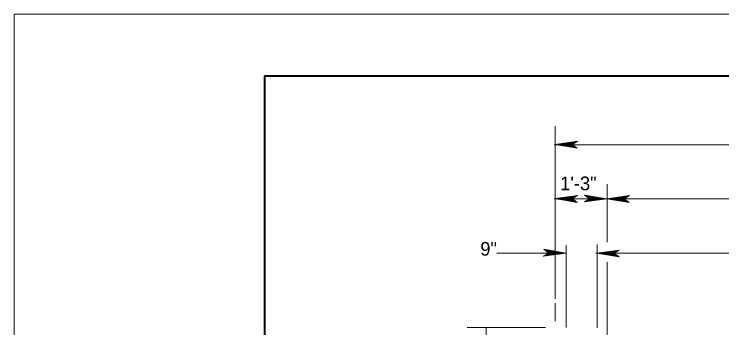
# Model space of a CAD drawing. Extents: x 144 to 252, y 360 to 425.
# Drawn here: x 143.81 to 160.77, y 417.96 to 425.48 of the extents above; entities that cross this region are included whole.
import ezdxf
from ezdxf.enums import TextEntityAlignment as Align

# ---------------------------------------------------------------- set-up
doc = ezdxf.new("R2010")
doc.units = 0
doc.header["$LTSCALE"] = 0.13
for name, color, linetype, lineweight in [('1', 7, 'Continuous', 40), ('16', 7, 'Continuous', 13), ('3', 7, 'Continuous', 13)]:
    doc.layers.add(name, color=color, linetype=linetype, lineweight=lineweight)

msp = doc.modelspace()

# ---------------------------------------------------------------- linework, layer by layer
at = {"layer": '1', "lineweight": 13}
for p, q in [((143.8112, 425.4823), (251.8112, 425.4823)), ((156.7812, 418.655), (156.7812, 421.0621)), ((157.7812, 419.2818), (157.7812, 419.9572)), ((157.0247, 419.7488), (155.3838, 419.7488)), ((177.7937, 419.7488), (157.751, 419.7488)), ((157.7812, 418.7965), (157.7812, 419.2818)), ((157.7812, 417.9642), (157.7812, 419.1343)), ((156.7812, 418.1206), (156.7812, 418.4672))]:
    msp.add_line(p, q, dxfattribs=at)
at = {"layer": '1'}
msp.add_lwpolyline([(250.3172, 361.9183), (250.3172, 423.9913), (149.8112, 423.9913), (149.8112, 361.9183), (230.3642, 361.9183)], dxfattribs=at)
at = {"layer": '16'}
msp.add_line((143.8112, 360.4183), (143.8112, 425.4823), dxfattribs=at)
at = {"layer": '3'}
for p, q in [((156.7812, 420.8483), (156.7812, 422.7941)), ((157.3177, 422.438), (156.7689, 422.3603)), ((156.7689, 422.3603), (157.3066, 422.271)), ((157.1843, 422.3603), (156.7689, 422.3603)), ((157.3117, 422.4345), (156.7833, 422.3596)), ((156.7833, 422.3596), (157.3033, 422.2733)), ((157.3082, 422.4325), (156.7942, 422.3596)), ((156.7942, 422.3596), (157.3001, 422.2757)), ((157.3036, 422.4298), (156.8086, 422.3596)), ((156.8086, 422.3596), (157.2958, 422.2788)), ((157.2995, 422.4274), (156.8213, 422.3596)), ((157.2995, 422.4274), (156.8213, 422.3596)), ((156.8213, 422.3596), (157.2921, 422.2815)), ((157.2958, 422.4253), (156.8327, 422.3596)), ((156.8327, 422.3596), (157.2887, 422.2839)), ((157.2912, 422.4226), (156.8471, 422.3596)), ((156.8471, 422.3596), (157.2845, 422.2871)), ((157.2872, 422.4202), (156.8598, 422.3596)), ((156.8598, 422.3596), (157.2807, 422.2898)), ((157.2827, 422.4177), (156.8736, 422.3596)), ((156.8736, 422.3596), (157.2767, 422.2928)), ((157.2783, 422.4151), (156.8874, 422.3596)), ((156.8874, 422.3596), (157.2726, 422.2957)), ((157.2741, 422.4126), (156.9007, 422.3596)), ((156.9007, 422.3596), (157.2687, 422.2986)), ((157.2696, 422.4099), (156.9146, 422.3596)), ((156.9146, 422.3596), (157.2646, 422.3016)), ((157.2656, 422.4077), (156.9272, 422.3596)), ((156.9272, 422.3596), (157.2608, 422.3042)), ((157.2618, 422.4054), (156.9386, 422.3596)), ((156.9386, 422.3596), (157.2574, 422.3067)), ((157.2568, 422.4026), (156.9543, 422.3596)), ((156.9543, 422.3596), (157.2528, 422.3101)), ((157.2524, 422.3999), (156.9681, 422.3596)), ((156.9681, 422.3596), (157.2488, 422.3131)), ((157.2452, 422.3957), (156.9861, 422.3591)), ((156.9861, 422.3591), (157.2445, 422.3162)), ((157.2484, 422.3977), (156.9877, 422.3607)), ((157.2408, 422.3932), (157, 422.3591)), ((157, 422.3591), (157.2403, 422.3192)), ((157.2366, 422.3907), (157.0132, 422.3591)), ((157.0132, 422.3591), (157.2365, 422.322)), ((157.2351, 422.3898), (157.0222, 422.3596)), ((157.0222, 422.3596), (157.2327, 422.3247)), ((157.2312, 422.3876), (157.0342, 422.3596)), ((157.0342, 422.3596), (157.2292, 422.3273)), ((157.2267, 422.3849), (157.0481, 422.3596)), ((157.0481, 422.3596), (157.2251, 422.3303)), ((157.2217, 422.3821), (157.0637, 422.3596)), ((157.0637, 422.3596), (157.2204, 422.3336)), ((157.2177, 422.3797), (157.0763, 422.3596)), ((157.0763, 422.3596), (157.2167, 422.3363)), ((157.2134, 422.3772), (157.0896, 422.3596)), ((157.0896, 422.3596), (157.2128, 422.3392)), ((157.2096, 422.3749), (157.1016, 422.3596)), ((157.1016, 422.3596), (157.2092, 422.3418)), ((157.2049, 422.3723), (157.1161, 422.3596)), ((157.1161, 422.3596), (157.205, 422.3448)), ((157.2005, 422.3697), (157.1299, 422.3596)), ((157.1299, 422.3596), (157.2008, 422.3478)), ((157.1964, 422.3673), (157.1426, 422.3596)), ((157.1426, 422.3596), (157.1972, 422.3506)), ((157.1558, 422.3596), (157.1933, 422.3534)), ((157.1912, 422.3642), (157.1661, 422.3607)), ((157.1885, 422.3627), (157.1672, 422.3596)), ((157.1672, 422.3596), (157.1898, 422.3558)), ((157.1774, 422.3596), (157.1868, 422.3581)), ((157.1841, 422.3601), (157.3177, 422.438)), ((157.3066, 422.271), (157.1841, 422.3601)), ((156.7562, 422.3458), (180.7569, 422.3458)), ((156.7812, 420.8483), (156.7812, 421.4067)), ((158.027, 420.0186), (158.027, 421.4067)), ((156.7571, 421.0507), (179.4617, 421.0507)), ((157.3188, 421.1359), (156.7701, 421.0582)), ((156.7701, 421.0582), (157.3077, 420.9689)), ((157.1855, 421.0582), (156.7701, 421.0582)), ((157.3128, 421.1324), (156.7845, 421.0575)), ((156.7845, 421.0575), (157.3045, 420.9712)), ((157.3093, 421.1304), (156.7953, 421.0575)), ((156.7953, 421.0575), (157.3012, 420.9736)), ((157.3047, 421.1277), (156.8098, 421.0575)), ((156.8098, 421.0575), (157.297, 420.9767)), ((157.3007, 421.1253), (156.8225, 421.0575)), ((157.3007, 421.1253), (156.8225, 421.0575)), ((156.8225, 421.0575), (157.2933, 420.9794)), ((157.297, 421.1232), (156.8338, 421.0575)), ((156.8338, 421.0575), (157.2899, 420.9818)), ((157.2924, 421.1205), (156.8483, 421.0575)), ((156.8483, 421.0575), (157.2857, 420.985)), ((157.2883, 421.1181), (156.861, 421.0575)), ((156.861, 421.0575), (157.2819, 420.9878)), ((157.2839, 421.1156), (156.8748, 421.0575)), ((156.8748, 421.0575), (157.2778, 420.9907)), ((157.2795, 421.113), (156.8886, 421.0575)), ((156.8886, 421.0575), (157.2738, 420.9937)), ((157.2752, 421.1105), (156.9018, 421.0575)), ((156.9018, 421.0575), (157.2698, 420.9965)), ((157.2707, 421.1078), (156.9158, 421.0575)), ((156.9158, 421.0575), (157.2657, 420.9995)), ((157.2668, 421.1056), (156.9283, 421.0575)), ((156.9283, 421.0575), (157.262, 421.0022)), ((157.263, 421.1033), (156.9398, 421.0575)), ((156.9398, 421.0575), (157.2586, 421.0047)), ((157.258, 421.1005), (156.9554, 421.0575)), ((156.9554, 421.0575), (157.254, 421.008)), ((157.2536, 421.0978), (156.9692, 421.0575)), ((156.9692, 421.0575), (157.2499, 421.011)), ((157.2464, 421.0937), (156.9872, 421.057)), ((156.9872, 421.057), (157.2457, 421.0141)), ((157.2496, 421.0956), (156.9888, 421.0586)), ((157.242, 421.0911), (157.0012, 421.057)), ((157.0012, 421.057), (157.2415, 421.0171)), ((157.2378, 421.0886), (157.0143, 421.057)), ((157.0143, 421.057), (157.2377, 421.0199)), ((157.2362, 421.0877), (157.0234, 421.0575)), ((157.0234, 421.0575), (157.2339, 421.0227)), ((157.2323, 421.0855), (157.0354, 421.0575)), ((157.0354, 421.0575), (157.2303, 421.0252)), ((157.2279, 421.0828), (157.0493, 421.0575)), ((157.0493, 421.0575), (157.2262, 421.0283)), ((157.2229, 421.08), (157.0649, 421.0575)), ((157.0649, 421.0575), (157.2216, 421.0315)), ((157.2188, 421.0776), (157.0775, 421.0575)), ((157.0775, 421.0575), (157.2179, 421.0342)), ((157.2146, 421.0751), (157.0907, 421.0575)), ((157.0907, 421.0575), (157.214, 421.0371)), ((157.2107, 421.0728), (157.1027, 421.0575)), ((157.1027, 421.0575), (157.2104, 421.0397)), ((157.2061, 421.0702), (157.1172, 421.0575)), ((157.1172, 421.0575), (157.2062, 421.0428)), ((157.2017, 421.0676), (157.1311, 421.0575)), ((157.1311, 421.0575), (157.202, 421.0457)), ((157.1976, 421.0652), (157.1437, 421.0575)), ((157.1437, 421.0575), (157.1983, 421.0485)), ((157.157, 421.0575), (157.1944, 421.0513)), ((157.1923, 421.0622), (157.1672, 421.0586)), ((157.1897, 421.0606), (157.1684, 421.0575)), ((157.1684, 421.0575), (157.191, 421.0537)), ((157.1786, 421.0575), (157.188, 421.056)), ((157.1852, 421.058), (157.3188, 421.1359)), ((157.3077, 420.9689), (157.1852, 421.058)), ((157.6057, 421.0566), (157.4721, 420.9787)), ((157.4721, 420.9787), (158.0208, 421.0564)), ((157.4781, 420.9822), (158.0064, 421.0571)), ((157.4816, 420.9842), (157.9956, 421.0571)), ((158.0208, 421.0564), (157.4832, 421.1457)), ((157.4832, 421.1457), (157.6057, 421.0566)), ((157.4862, 420.9868), (157.9812, 421.0571)), ((158.0064, 421.0571), (157.4864, 421.1433)), ((157.9956, 421.0571), (157.4897, 421.141)), ((157.4903, 420.9892), (157.9684, 421.0571)), ((157.4903, 420.9892), (157.9684, 421.0571)), ((157.9812, 421.0571), (157.4939, 421.1378)), ((157.4939, 420.9914), (157.9571, 421.0571)), ((157.9684, 421.0571), (157.4977, 421.1352)), ((157.4985, 420.9941), (157.9427, 421.0571)), ((157.9571, 421.0571), (157.501, 421.1327)), ((157.5026, 420.9965), (157.9299, 421.0571)), ((157.9427, 421.0571), (157.5052, 421.1296)), ((157.507, 420.999), (157.9162, 421.0571)), ((157.9299, 421.0571), (157.509, 421.1268)), ((157.5114, 421.0016), (157.9023, 421.0571)), ((157.9162, 421.0571), (157.5131, 421.1239)), ((157.5157, 421.0041), (157.8891, 421.0571)), ((157.9023, 421.0571), (157.5172, 421.1209)), ((157.5202, 421.0068), (157.8752, 421.0571)), ((157.8891, 421.0571), (157.5211, 421.1181)), ((157.5242, 421.009), (157.8626, 421.0571)), ((157.8752, 421.0571), (157.5252, 421.1151)), ((157.5279, 421.0112), (157.8512, 421.0571)), ((157.8626, 421.0571), (157.5289, 421.1124)), ((157.8512, 421.0571), (157.5323, 421.1099)), ((157.5329, 421.0141), (157.8355, 421.0571)), ((157.8355, 421.0571), (157.5369, 421.1066)), ((157.5373, 421.0168), (157.8217, 421.0571)), ((157.8217, 421.0571), (157.541, 421.1036)), ((157.5413, 421.019), (157.8021, 421.056)), ((157.5445, 421.0209), (157.8037, 421.0576)), ((157.8037, 421.0576), (157.5452, 421.1005)), ((157.5489, 421.0235), (157.7897, 421.0576)), ((157.7897, 421.0576), (157.5494, 421.0975)), ((157.7766, 421.0576), (157.5532, 421.0947)), ((157.5532, 421.026), (157.7766, 421.0576)), ((157.5547, 421.0268), (157.7675, 421.0571)), ((157.7675, 421.0571), (157.557, 421.0919)), ((157.5586, 421.0291), (157.7555, 421.0571)), ((157.7555, 421.0571), (157.5606, 421.0893)), ((157.563, 421.0317), (157.7417, 421.0571)), ((157.7417, 421.0571), (157.5647, 421.0863)), ((157.568, 421.0346), (157.726, 421.0571)), ((157.726, 421.0571), (157.5693, 421.0831)), ((157.5721, 421.037), (157.7134, 421.0571)), ((157.7134, 421.0571), (157.573, 421.0803)), ((157.5763, 421.0395), (157.7002, 421.0571)), ((157.7002, 421.0571), (157.5769, 421.0775)), ((157.5802, 421.0417), (157.6882, 421.0571)), ((157.6882, 421.0571), (157.5805, 421.0748)), ((157.6737, 421.0571), (157.5847, 421.0718)), ((157.5848, 421.0444), (157.6737, 421.0571)), ((157.6598, 421.0571), (157.5889, 421.0688)), ((157.5892, 421.047), (157.6598, 421.0571)), ((157.6472, 421.0571), (157.5926, 421.0661)), ((157.5933, 421.0493), (157.6472, 421.0571)), ((157.6339, 421.0571), (157.5965, 421.0632)), ((157.5986, 421.0524), (157.6237, 421.056)), ((157.6225, 421.0571), (157.5999, 421.0608)), ((157.6012, 421.054), (157.6225, 421.0571)), ((157.6123, 421.0571), (157.6029, 421.0586)), ((157.6054, 421.0564), (158.0208, 421.0564)), ((158.5622, 421.1342), (158.0134, 421.0564)), ((158.0134, 421.0564), (158.5511, 420.9672)), ((158.4288, 421.0564), (158.0134, 421.0564)), ((158.5562, 421.1307), (158.0278, 421.0557)), ((158.0278, 421.0557), (158.5478, 420.9695)), ((158.5527, 421.1287), (158.0387, 421.0557)), ((158.0387, 421.0557), (158.5446, 420.9718)), ((158.5481, 421.126), (158.0531, 421.0557)), ((158.0531, 421.0557), (158.5403, 420.975)), ((158.544, 421.1236), (158.0658, 421.0557)), ((158.544, 421.1236), (158.0658, 421.0557)), ((158.0658, 421.0557), (158.5366, 420.9777)), ((158.5403, 421.1214), (158.0772, 421.0557)), ((158.0772, 421.0557), (158.5332, 420.9801)), ((158.5358, 421.1187), (158.0916, 421.0557)), ((158.0916, 421.0557), (158.529, 420.9832)), ((158.5317, 421.1163), (158.1043, 421.0557)), ((158.1043, 421.0557), (158.5252, 420.986)), ((158.5272, 421.1138), (158.1181, 421.0557)), ((158.1181, 421.0557), (158.5212, 420.9889)), ((158.5228, 421.1112), (158.1319, 421.0557)), ((158.1319, 421.0557), (158.5171, 420.9919)), ((158.5186, 421.1087), (158.1452, 421.0557)), ((158.1452, 421.0557), (158.5132, 420.9948)), ((158.5141, 421.1061), (158.1591, 421.0557)), ((158.1591, 421.0557), (158.5091, 420.9977)), ((158.5101, 421.1038), (158.1717, 421.0557)), ((158.1717, 421.0557), (158.5053, 421.0004)), ((158.5063, 421.1016), (158.1831, 421.0557)), ((158.1831, 421.0557), (158.5019, 421.0029)), ((158.5013, 421.0987), (158.1987, 421.0557)), ((158.1987, 421.0557), (158.4973, 421.0062)), ((158.4969, 421.0961), (158.2126, 421.0557)), ((158.2126, 421.0557), (158.4932, 421.0093)), ((158.4897, 421.0919), (158.2306, 421.0553)), ((158.2306, 421.0553), (158.489, 421.0123)), ((158.4929, 421.0938), (158.2322, 421.0568)), ((158.4853, 421.0893), (158.2445, 421.0553)), ((158.2445, 421.0553), (158.4848, 421.0153)), ((158.4811, 421.0868), (158.2577, 421.0553)), ((158.2577, 421.0553), (158.481, 421.0182)), ((158.4796, 421.086), (158.2668, 421.0557)), ((158.2668, 421.0557), (158.4772, 421.0209)), ((158.4757, 421.0838), (158.2788, 421.0557)), ((158.2788, 421.0557), (158.4737, 421.0235)), ((158.4712, 421.0811), (158.2926, 421.0557)), ((158.2926, 421.0557), (158.4696, 421.0265)), ((158.4663, 421.0782), (158.3082, 421.0557)), ((158.3082, 421.0557), (158.4649, 421.0297)), ((158.4622, 421.0758), (158.3208, 421.0557)), ((158.3208, 421.0557), (158.4613, 421.0325)), ((158.4579, 421.0733), (158.3341, 421.0557)), ((158.3341, 421.0557), (158.4573, 421.0353)), ((158.4541, 421.0711), (158.3461, 421.0557)), ((158.3461, 421.0557), (158.4537, 421.038)), ((158.4494, 421.0684), (158.3606, 421.0557)), ((158.3606, 421.0557), (158.4495, 421.041)), ((158.445, 421.0658), (158.3744, 421.0557)), ((158.3744, 421.0557), (158.4453, 421.044)), ((158.4409, 421.0635), (158.3871, 421.0557)), ((158.3871, 421.0557), (158.4417, 421.0467)), ((158.4003, 421.0557), (158.4377, 421.0496)), ((158.4357, 421.0604), (158.4106, 421.0568)), ((158.433, 421.0588), (158.4117, 421.0557)), ((158.4117, 421.0557), (158.4343, 421.052)), ((158.4219, 421.0557), (158.4313, 421.0542)), ((158.4286, 421.0562), (158.5622, 421.1342)), ((158.5511, 420.9672), (158.4286, 421.0562)), ((156.7812, 420.8483), (156.7812, 420.9528)), ((156.7812, 420.7998), (156.7812, 420.9528)), ((158.027, 420.8356), (158.027, 420.9528)), ((157.043, 419.7543), (156.5053, 419.8436)), ((156.5053, 419.8436), (156.6278, 419.7545)), ((157.0286, 419.755), (156.5086, 419.8413)), ((157.0178, 419.755), (156.5118, 419.8389)), ((157.0033, 419.755), (156.5161, 419.8357)), ((156.9906, 419.755), (156.5198, 419.8331)), ((156.9793, 419.755), (156.5232, 419.8307)), ((156.9648, 419.755), (156.5274, 419.8275)), ((156.9521, 419.755), (156.5312, 419.8247)), ((156.9383, 419.755), (156.5352, 419.8218)), ((156.9245, 419.755), (156.5393, 419.8188)), ((156.9112, 419.755), (156.5433, 419.816)), ((156.8973, 419.755), (156.5473, 419.813)), ((156.8847, 419.755), (156.5511, 419.8103)), ((156.8733, 419.755), (156.5545, 419.8078)), ((157.0457, 417.9721), (157.0457, 419.9424)), ((158.3201, 419.8268), (157.7713, 419.749)), ((158.3141, 419.8232), (157.7858, 419.7483)), ((158.3106, 419.8212), (157.7966, 419.7483)), ((158.306, 419.8186), (157.811, 419.7483)), ((158.3019, 419.8162), (157.8237, 419.7483)), ((158.3019, 419.8162), (157.8237, 419.7483)), ((158.2982, 419.814), (157.8351, 419.7483)), ((158.2937, 419.8113), (157.8495, 419.7483)), ((158.2896, 419.8089), (157.8622, 419.7483)), ((158.2852, 419.8064), (157.876, 419.7483)), ((158.1865, 419.7488), (158.3201, 419.8268)), ((156.6278, 419.7545), (156.4942, 419.6766)), ((156.4942, 419.6766), (157.043, 419.7543)), ((156.5002, 419.6801), (157.0286, 419.755)), ((156.5037, 419.6821), (157.0178, 419.755)), ((156.5083, 419.6848), (157.0033, 419.755)), ((156.5124, 419.6872), (156.9906, 419.755)), ((156.5124, 419.6872), (156.9906, 419.755)), ((156.5161, 419.6893), (156.9793, 419.755)), ((156.5207, 419.692), (156.9648, 419.755)), ((156.5247, 419.6944), (156.9521, 419.755)), ((156.5292, 419.6969), (156.9383, 419.755)), ((156.5336, 419.6995), (156.9245, 419.755)), ((156.5378, 419.702), (156.9112, 419.755)), ((156.5423, 419.7047), (156.8973, 419.755)), ((156.5463, 419.7069), (156.8847, 419.755)), ((156.5501, 419.7092), (156.8733, 419.755)), ((156.5551, 419.712), (156.8577, 419.755)), ((156.8577, 419.755), (156.5591, 419.8045)), ((156.5595, 419.7147), (156.8438, 419.755)), ((156.8438, 419.755), (156.5632, 419.8015)), ((156.5635, 419.7169), (156.8243, 419.7539)), ((156.5667, 419.7188), (156.8258, 419.7555)), ((156.8258, 419.7555), (156.5674, 419.7984)), ((156.5711, 419.7214), (156.8119, 419.7555)), ((156.8119, 419.7555), (156.5716, 419.7954)), ((156.5753, 419.7239), (156.7987, 419.7555)), ((156.7987, 419.7555), (156.5754, 419.7926)), ((156.5768, 419.7247), (156.7897, 419.755)), ((156.7897, 419.755), (156.5792, 419.7898)), ((156.5807, 419.727), (156.7777, 419.755)), ((156.7777, 419.755), (156.5828, 419.7872)), ((156.5852, 419.7297), (156.7638, 419.755)), ((156.7638, 419.755), (156.5868, 419.7842)), ((156.5902, 419.7325), (156.7482, 419.755)), ((156.7482, 419.755), (156.5915, 419.781)), ((156.5942, 419.7349), (156.7356, 419.755)), ((156.7356, 419.755), (156.5952, 419.7783)), ((156.5985, 419.7374), (156.7223, 419.755)), ((156.7223, 419.755), (156.5991, 419.7754)), ((156.6023, 419.7397), (156.7103, 419.755)), ((156.7103, 419.755), (156.6027, 419.7727)), ((156.6958, 419.755), (156.6069, 419.7697)), ((156.607, 419.7423), (156.6958, 419.755)), ((156.682, 419.755), (156.6111, 419.7668)), ((156.6114, 419.7449), (156.682, 419.755)), ((156.6693, 419.755), (156.6147, 419.764)), ((156.6155, 419.7473), (156.6693, 419.755)), ((156.6561, 419.755), (156.6187, 419.7612)), ((156.6207, 419.7503), (156.6458, 419.7539)), ((156.6447, 419.755), (156.6221, 419.7587)), ((156.6234, 419.7519), (156.6447, 419.755)), ((156.6345, 419.755), (156.6251, 419.7565)), ((156.6276, 419.7543), (157.043, 419.7543)), ((156.7812, 418.655), (156.7812, 419.6534)), ((157.7713, 419.749), (158.309, 419.6597)), ((158.1867, 419.749), (157.7713, 419.749)), ((157.7858, 419.7483), (158.3057, 419.6621)), ((157.7966, 419.7483), (158.3025, 419.6644)), ((157.811, 419.7483), (158.2982, 419.6676)), ((157.8237, 419.7483), (158.2945, 419.6703)), ((157.8351, 419.7483), (158.2912, 419.6727)), ((157.8495, 419.7483), (158.2869, 419.6758)), ((157.8622, 419.7483), (158.2832, 419.6786)), ((157.876, 419.7483), (158.2791, 419.6815)), ((158.2807, 419.8038), (157.8898, 419.7483)), ((157.8898, 419.7483), (158.275, 419.6845)), ((158.2765, 419.8013), (157.9031, 419.7483)), ((157.9031, 419.7483), (158.2711, 419.6873)), ((158.272, 419.7987), (157.917, 419.7483)), ((157.917, 419.7483), (158.267, 419.6903)), ((158.268, 419.7964), (157.9296, 419.7483)), ((157.9296, 419.7483), (158.2632, 419.693)), ((158.2643, 419.7942), (157.941, 419.7483)), ((157.941, 419.7483), (158.2598, 419.6955)), ((158.2593, 419.7913), (157.9567, 419.7483)), ((157.9567, 419.7483), (158.2552, 419.6988)), ((158.2548, 419.7887), (157.9705, 419.7483)), ((157.9705, 419.7483), (158.2512, 419.7018)), ((158.2477, 419.7845), (157.9885, 419.7478)), ((157.9885, 419.7478), (158.2469, 419.7049)), ((158.2508, 419.7864), (157.9901, 419.7494)), ((158.2432, 419.7819), (158.0024, 419.7478)), ((158.0024, 419.7478), (158.2428, 419.7079)), ((158.239, 419.7794), (158.0156, 419.7478)), ((158.0156, 419.7478), (158.2389, 419.7107)), ((158.2375, 419.7786), (158.0247, 419.7483)), ((158.0247, 419.7483), (158.2352, 419.7135)), ((158.2336, 419.7763), (158.0367, 419.7483)), ((158.0367, 419.7483), (158.2316, 419.7161)), ((158.2292, 419.7737), (158.0505, 419.7483)), ((158.0505, 419.7483), (158.2275, 419.7191)), ((158.2242, 419.7708), (158.0662, 419.7483)), ((158.0662, 419.7483), (158.2228, 419.7223)), ((158.2201, 419.7684), (158.0787, 419.7483)), ((158.0787, 419.7483), (158.2192, 419.7251)), ((158.2158, 419.7659), (158.092, 419.7483)), ((158.092, 419.7483), (158.2152, 419.7279)), ((158.212, 419.7637), (158.104, 419.7483)), ((158.104, 419.7483), (158.2117, 419.7306)), ((158.2073, 419.761), (158.1185, 419.7483)), ((158.1185, 419.7483), (158.2074, 419.7336)), ((158.2029, 419.7584), (158.1323, 419.7483)), ((158.1323, 419.7483), (158.2032, 419.7366)), ((158.1988, 419.7561), (158.145, 419.7483)), ((158.145, 419.7483), (158.1996, 419.7393)), ((158.1582, 419.7483), (158.1957, 419.7422)), ((158.1936, 419.753), (158.1685, 419.7494)), ((158.1909, 419.7514), (158.1697, 419.7483)), ((158.1697, 419.7483), (158.1923, 419.7446)), ((158.1798, 419.7483), (158.1892, 419.7468)), ((158.309, 419.6597), (158.1865, 419.7488)), ((156.7812, 418.655), (156.7812, 419.6131)), ((158.027, 419.2691), (158.027, 419.5367)), ((158.027, 418.8672), (158.027, 419.2691)), ((158.027, 416.8755), (158.027, 419.1343)), ((156.7812, 418.4539), (156.7812, 418.5505)), ((156.7812, 418.1206), (156.7812, 418.4672)), ((156.5439, 417.9673), (154.6723, 417.9673)), ((155.1215, 416.5902), (155.1215, 417.9803))]:
    msp.add_line(p, q, dxfattribs=at)

# ---------------------------------------------------------------- texts
at = {"layer": '16'}
msp.add_text('1\'-3"', height=0.3281, dxfattribs=at).set_placement((157.3357, 421.2607), align=Align.CENTER)
msp.add_text('9"', height=0.3281, dxfattribs=at).set_placement((154.9834, 419.6914))

doc.saveas('drawing.dxf')
